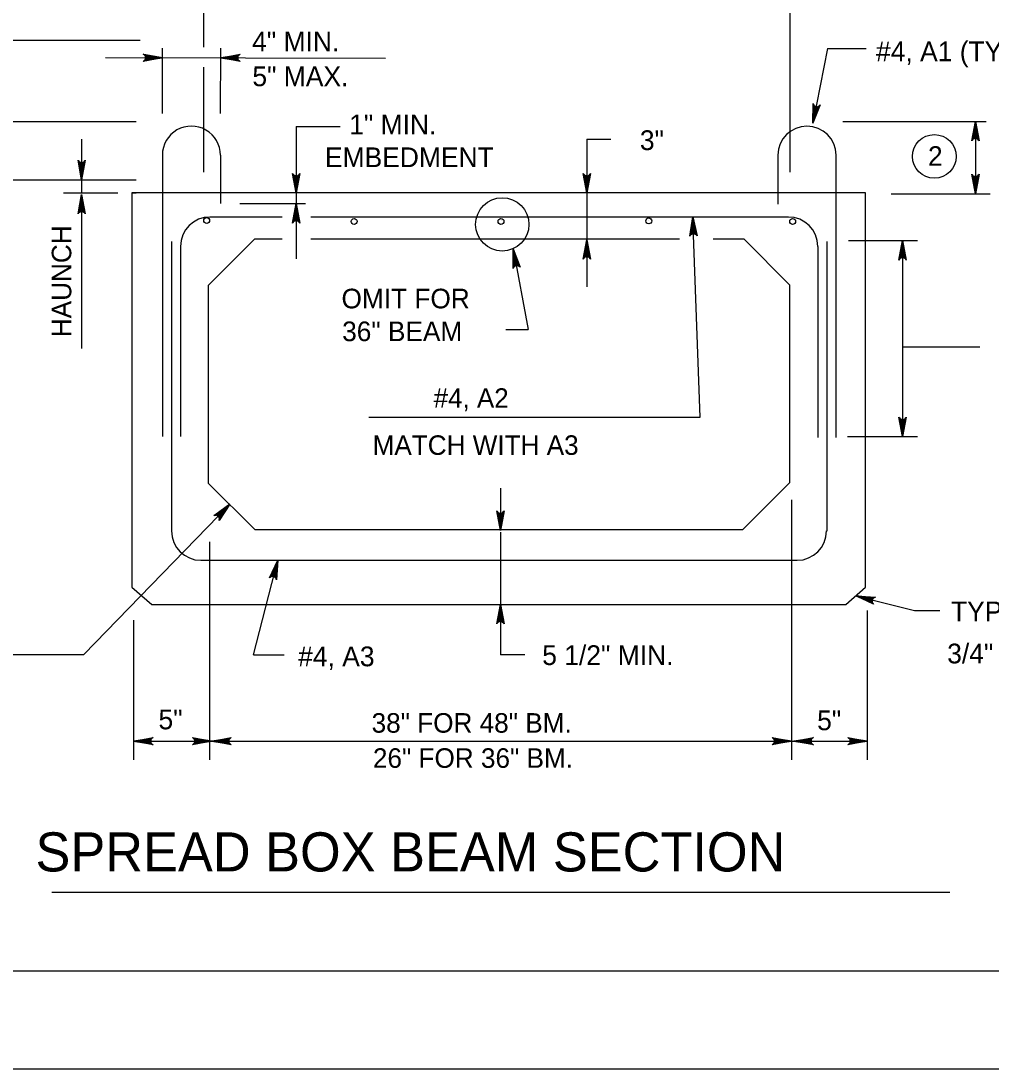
# Model space of a CAD drawing. Extents: x 639331 to 643089, y 299088 to 300975.
# Drawn here: x 641530.2 to 641679, y 299087.7 to 299248.4 of the extents above; entities that cross this region are included whole.
import ezdxf

# ---------------------------------------------------------------- set-up
doc = ezdxf.new("R2010")
doc.units = 0
doc.layers.add('1', color=7, linetype='Continuous')
doc.layers.add('PLT-BNDY', color=7, linetype='Continuous')

msp = doc.modelspace()

# ---------------------------------------------------------------- linework, layer by layer
at = {"layer": '1'}
for p, q in [((641558.17, 299256.75), (641558.17, 299244.44)), ((641648.09, 299256.75), (641648.09, 299225.23)), ((641548.44, 299245.44), (641512.84, 299245.44)), ((641551.86, 299234.24), (641551.88, 299244.3)), ((641560.77, 299234.23), (641560.79, 299244.28)), ((641653.87, 299244.2), (641651.62, 299232.75)), ((641653.87, 299244.2), (641659.79, 299244.2)), ((641543.1, 299242.82), (641586.08, 299242.75)), ((641558.17, 299241.34), (641558.17, 299225.23)), ((641512.84, 299233.04), (641547.81, 299233.04)), ((641656.21, 299233.04), (641678.19, 299233.04)), ((641676.55, 299233.04), (641676.55, 299221.95)), ((641572.36, 299232.24), (641579.09, 299232.24)), ((641572.36, 299232.24), (641572.36, 299220.42)), ((641539.46, 299230.34), (641539.46, 299222.08)), ((641616.95, 299230.29), (641620.61, 299230.29)), ((641616.95, 299230.29), (641616.95, 299222.08)), ((641551.84, 299227.86), (641551.84, 299184.69)), ((641560.75, 299227.85), (641560.75, 299220.42)), ((641646.26, 299227.86), (641646.26, 299220.36)), ((641655.17, 299227.86), (641655.17, 299184.57)), ((641512.84, 299224.1), (641547.81, 299224.1)), ((641536.69, 299222.08), (641545.03, 299222.08)), ((641539.46, 299221.83), (641539.46, 299198.2)), ((641659.71, 299222.08), (641547.18, 299222.08)), ((641547.18, 299222.08), (641547.18, 299161.58)), ((641547.18, 299222.08), (641547.81, 299222.08)), ((641616.95, 299222.08), (641616.95, 299215.01)), ((641659.71, 299161.58), (641659.71, 299222.08)), ((641663.62, 299221.95), (641678.8, 299221.95)), ((641563.74, 299220.42), (641573.78, 299220.42)), ((641572.36, 299220.42), (641572.36, 299211.97)), ((641559.14, 299218.42), (641570.23, 299218.42)), ((641574.64, 299218.42), (641647.87, 299218.42)), ((641634.33, 299187.69), (641633.19, 299218.42)), ((641558.8, 299218.16), (641558.8, 299218.16)), ((641581.28, 299218.04), (641581.28, 299218.04)), ((641603.89, 299217.91), (641603.89, 299217.91)), ((641626.37, 299217.78), (641626.37, 299217.78)), ((641648.97, 299217.66), (641648.97, 299217.66)), ((641551.84, 299214.63), (641551.84, 299184.69)), ((641553.24, 299214.63), (641553.24, 299170.17)), ((641554.64, 299213.87), (641554.64, 299184.69)), ((641558.92, 299207.93), (641566, 299215.01)), ((641566, 299215.01), (641570.23, 299215.01)), ((641574.64, 299215.01), (641631.17, 299215.01)), ((641616.95, 299215.01), (641616.95, 299207.68)), ((641636.33, 299215.01), (641641.02, 299215.01)), ((641641.02, 299215.01), (641648.09, 299207.93)), ((641652.37, 299213.87), (641652.37, 299184.57)), ((641653.77, 299214.63), (641653.77, 299170.17)), ((641657.09, 299214.75), (641667.66, 299214.75)), ((641665.39, 299214.75), (641665.39, 299184.68)), ((641605.65, 299213.49), (641607.93, 299201.11)), ((641558.92, 299177.5), (641558.92, 299207.93)), ((641648.09, 299177.62), (641648.09, 299207.93)), ((641604.52, 299201.11), (641607.93, 299201.11)), ((641665.39, 299198.46), (641677.24, 299198.46)), ((641583.52, 299187.69), (641634.33, 299187.69)), ((641656.93, 299184.68), (641667.66, 299184.68)), ((641558.92, 299177.5), (641566, 299170.42)), ((641603.69, 299176.76), (641603.69, 299170.3)), ((641640.89, 299170.42), (641648.09, 299177.62)), ((641562.21, 299174.34), (641539.79, 299151.28)), ((641648.34, 299174.97), (641648.34, 299135.12)), ((641566, 299170.42), (641640.89, 299170.42)), ((641603.69, 299170.04), (641603.69, 299158.93)), ((641559.05, 299168.53), (641559.05, 299135.12)), ((641557.79, 299165.75), (641649.22, 299165.75)), ((641565.81, 299151.18), (641569.53, 299165.75)), ((641547.18, 299161.58), (641550.21, 299158.93)), ((641656.68, 299158.93), (641659.71, 299161.58)), ((641550.21, 299158.93), (641656.68, 299158.93)), ((641603.69, 299158.93), (641603.69, 299158.8)), ((641603.69, 299158.93), (641603.69, 299151.18)), ((641658.19, 299160.26), (641667.19, 299157.98)), ((641659.96, 299158.02), (641659.96, 299135.12)), ((641667.19, 299157.98), (641671.12, 299157.98)), ((641547.43, 299156.53), (641547.43, 299135.12)), ((641524.47, 299151.28), (641539.79, 299151.28)), ((641565.81, 299151.18), (641570.54, 299151.18)), ((641607.46, 299151.18), (641603.69, 299151.18)), ((641547.43, 299137.96), (641559.43, 299137.96)), ((641559.43, 299137.96), (641648.72, 299137.96)), ((641648.72, 299137.96), (641659.96, 299137.96)), ((641672.61, 299114.74), (641534.91, 299114.74)), ((642219.06, 299102.66), (641433.06, 299102.66))]:
    msp.add_line(p, q, dxfattribs=at)
for points in [[(641551.88, 299242.81), (641548.89, 299242.25), (641549.01, 299242.33), (641549.12, 299242.41), (641549.18, 299242.51), (641549.24, 299242.61), (641549.26, 299242.71), (641549.28, 299242.81), (641549.26, 299242.91), (641549.24, 299243.01), (641549.18, 299243.11), (641549.12, 299243.21), (641549.01, 299243.29), (641548.9, 299243.37), (641551.88, 299242.81), (641549.01, 299243.29), (641549.12, 299243.21), (641551.88, 299242.81), (641549.18, 299243.11), (641549.24, 299243.01), (641551.88, 299242.81), (641549.26, 299242.91), (641549.28, 299242.81), (641551.88, 299242.81), (641549.26, 299242.71), (641549.24, 299242.61), (641551.88, 299242.81), (641549.18, 299242.51), (641549.12, 299242.41), (641551.88, 299242.81), (641549.01, 299242.33)], [(641560.79, 299242.79), (641563.77, 299243.35), (641563.66, 299243.27), (641563.54, 299243.19), (641563.48, 299243.09), (641563.42, 299242.99), (641563.4, 299242.89), (641563.39, 299242.79), (641563.4, 299242.69), (641563.42, 299242.59), (641563.48, 299242.49), (641563.54, 299242.39), (641563.65, 299242.31), (641563.77, 299242.23), (641560.79, 299242.79), (641563.65, 299242.31), (641563.54, 299242.39), (641560.79, 299242.79), (641563.48, 299242.49), (641563.42, 299242.59), (641560.79, 299242.79), (641563.4, 299242.69), (641563.39, 299242.79), (641560.79, 299242.79), (641563.4, 299242.89), (641563.42, 299242.99), (641560.79, 299242.79), (641563.48, 299243.09), (641563.54, 299243.19), (641560.79, 299242.79), (641563.66, 299243.27)], [(641651.62, 299232.75), (641651.65, 299235.79), (641651.7, 299235.66), (641651.76, 299235.53), (641651.85, 299235.45), (641651.93, 299235.38), (641652.03, 299235.34), (641652.12, 299235.3), (641652.22, 299235.3), (641652.33, 299235.3), (641652.43, 299235.34), (641652.54, 299235.38), (641652.64, 299235.48), (641652.74, 299235.57), (641651.62, 299232.75), (641652.64, 299235.48), (641652.54, 299235.38), (641651.62, 299232.75), (641652.43, 299235.34), (641652.33, 299235.3), (641651.62, 299232.75), (641652.22, 299235.3), (641652.12, 299235.3), (641651.62, 299232.75), (641652.03, 299235.34), (641651.93, 299235.38), (641651.62, 299232.75), (641651.85, 299235.45), (641651.76, 299235.53), (641651.62, 299232.75), (641651.7, 299235.66)], [(641676.55, 299233.04), (641677.11, 299230.06), (641677.03, 299230.17), (641676.95, 299230.29), (641676.85, 299230.35), (641676.75, 299230.41), (641676.65, 299230.42), (641676.55, 299230.44), (641676.45, 299230.42), (641676.35, 299230.41), (641676.25, 299230.35), (641676.15, 299230.29), (641676.07, 299230.17), (641675.99, 299230.06), (641676.55, 299233.04), (641676.07, 299230.17), (641676.15, 299230.29), (641676.55, 299233.04), (641676.25, 299230.35), (641676.35, 299230.41), (641676.55, 299233.04), (641676.45, 299230.42), (641676.55, 299230.44), (641676.55, 299233.04), (641676.65, 299230.42), (641676.75, 299230.41), (641676.55, 299233.04), (641676.85, 299230.35), (641676.95, 299230.29), (641676.55, 299233.04), (641677.03, 299230.17)], [(641539.46, 299224.1), (641538.91, 299227.08), (641538.98, 299226.97), (641539.06, 299226.85), (641539.16, 299226.79), (641539.26, 299226.73), (641539.36, 299226.72), (641539.46, 299226.7), (641539.56, 299226.72), (641539.66, 299226.73), (641539.76, 299226.79), (641539.86, 299226.85), (641539.94, 299226.97), (641540.02, 299227.08), (641539.46, 299224.1), (641539.94, 299226.97), (641539.86, 299226.85), (641539.46, 299224.1), (641539.76, 299226.79), (641539.66, 299226.73), (641539.46, 299224.1), (641539.56, 299226.72), (641539.46, 299226.7), (641539.46, 299224.1), (641539.36, 299226.72), (641539.26, 299226.73), (641539.46, 299224.1), (641539.16, 299226.79), (641539.06, 299226.85), (641539.46, 299224.1), (641538.98, 299226.97)], [(641572.36, 299222.08), (641571.8, 299225.06), (641571.88, 299224.95), (641571.96, 299224.83), (641572.06, 299224.77), (641572.16, 299224.71), (641572.26, 299224.7), (641572.36, 299224.68), (641572.46, 299224.7), (641572.56, 299224.71), (641572.66, 299224.77), (641572.76, 299224.83), (641572.84, 299224.95), (641572.92, 299225.06), (641572.36, 299222.08), (641572.84, 299224.95), (641572.76, 299224.83), (641572.36, 299222.08), (641572.66, 299224.77), (641572.56, 299224.71), (641572.36, 299222.08), (641572.46, 299224.7), (641572.36, 299224.68), (641572.36, 299222.08), (641572.26, 299224.7), (641572.16, 299224.71), (641572.36, 299222.08), (641572.06, 299224.77), (641571.96, 299224.83), (641572.36, 299222.08), (641571.88, 299224.95)], [(641616.95, 299222.08), (641616.39, 299225.06), (641616.47, 299224.95), (641616.55, 299224.83), (641616.65, 299224.77), (641616.75, 299224.71), (641616.85, 299224.7), (641616.95, 299224.68), (641617.05, 299224.7), (641617.15, 299224.71), (641617.25, 299224.77), (641617.35, 299224.83), (641617.43, 299224.95), (641617.51, 299225.06), (641616.95, 299222.08), (641617.43, 299224.95), (641617.35, 299224.83), (641616.95, 299222.08), (641617.25, 299224.77), (641617.15, 299224.71), (641616.95, 299222.08), (641617.05, 299224.7), (641616.95, 299224.68), (641616.95, 299222.08), (641616.85, 299224.7), (641616.75, 299224.71), (641616.95, 299222.08), (641616.65, 299224.77), (641616.55, 299224.83), (641616.95, 299222.08), (641616.47, 299224.95)], [(641676.55, 299221.95), (641675.99, 299224.93), (641676.07, 299224.82), (641676.15, 299224.7), (641676.25, 299224.65), (641676.35, 299224.59), (641676.45, 299224.57), (641676.55, 299224.55), (641676.65, 299224.57), (641676.75, 299224.59), (641676.85, 299224.65), (641676.95, 299224.7), (641677.03, 299224.82), (641677.11, 299224.93), (641676.55, 299221.95), (641677.03, 299224.82), (641676.95, 299224.7), (641676.55, 299221.95), (641676.85, 299224.65), (641676.75, 299224.59), (641676.55, 299221.95), (641676.65, 299224.57), (641676.55, 299224.55), (641676.55, 299221.95), (641676.45, 299224.57), (641676.35, 299224.59), (641676.55, 299221.95), (641676.25, 299224.65), (641676.15, 299224.7), (641676.55, 299221.95), (641676.07, 299224.82)], [(641539.46, 299221.83), (641540.02, 299218.84), (641539.94, 299218.96), (641539.86, 299219.07), (641539.76, 299219.13), (641539.66, 299219.19), (641539.56, 299219.21), (641539.46, 299219.22), (641539.36, 299219.21), (641539.26, 299219.19), (641539.16, 299219.13), (641539.06, 299219.07), (641538.98, 299218.96), (641538.91, 299218.84), (641539.46, 299221.83), (641538.98, 299218.96), (641539.06, 299219.07), (641539.46, 299221.83), (641539.16, 299219.13), (641539.26, 299219.19), (641539.46, 299221.83), (641539.36, 299219.21), (641539.46, 299219.22), (641539.46, 299221.83), (641539.56, 299219.21), (641539.66, 299219.19), (641539.46, 299221.83), (641539.76, 299219.13), (641539.86, 299219.07), (641539.46, 299221.83), (641539.94, 299218.96)], [(641572.36, 299220.42), (641572.92, 299217.43), (641572.84, 299217.55), (641572.76, 299217.66), (641572.66, 299217.72), (641572.56, 299217.78), (641572.46, 299217.8), (641572.36, 299217.82), (641572.26, 299217.8), (641572.16, 299217.78), (641572.06, 299217.72), (641571.96, 299217.66), (641571.88, 299217.55), (641571.8, 299217.43), (641572.36, 299220.42), (641571.88, 299217.55), (641571.96, 299217.66), (641572.36, 299220.42), (641572.06, 299217.72), (641572.16, 299217.78), (641572.36, 299220.42), (641572.26, 299217.8), (641572.36, 299217.82), (641572.36, 299220.42), (641572.46, 299217.8), (641572.56, 299217.78), (641572.36, 299220.42), (641572.66, 299217.72), (641572.76, 299217.66), (641572.36, 299220.42), (641572.84, 299217.55)], [(641633.19, 299218.42), (641633.86, 299215.46), (641633.77, 299215.57), (641633.69, 299215.68), (641633.59, 299215.73), (641633.48, 299215.79), (641633.38, 299215.8), (641633.28, 299215.82), (641633.18, 299215.8), (641633.08, 299215.77), (641632.99, 299215.71), (641632.89, 299215.65), (641632.81, 299215.53), (641632.74, 299215.41), (641633.19, 299218.42), (641632.81, 299215.53), (641632.89, 299215.65), (641633.19, 299218.42), (641632.99, 299215.71), (641633.08, 299215.77), (641633.19, 299218.42), (641633.18, 299215.8), (641633.28, 299215.82), (641633.19, 299218.42), (641633.38, 299215.8), (641633.48, 299215.79), (641633.19, 299218.42), (641633.59, 299215.73), (641633.69, 299215.68), (641633.19, 299218.42), (641633.77, 299215.57)], [(641616.95, 299214.88), (641617.51, 299211.9), (641617.43, 299212.01), (641617.35, 299212.13), (641617.25, 299212.19), (641617.15, 299212.24), (641617.05, 299212.26), (641616.95, 299212.28), (641616.85, 299212.26), (641616.75, 299212.24), (641616.65, 299212.19), (641616.55, 299212.13), (641616.47, 299212.01), (641616.39, 299211.9), (641616.95, 299214.88), (641616.47, 299212.01), (641616.55, 299212.13), (641616.95, 299214.88), (641616.65, 299212.19), (641616.75, 299212.24), (641616.95, 299214.88), (641616.85, 299212.26), (641616.95, 299212.28), (641616.95, 299214.88), (641617.05, 299212.26), (641617.15, 299212.24), (641616.95, 299214.88), (641617.25, 299212.19), (641617.35, 299212.13), (641616.95, 299214.88), (641617.43, 299212.01)], [(641665.39, 299214.75), (641665.95, 299211.77), (641665.87, 299211.88), (641665.79, 299212), (641665.69, 299212.06), (641665.59, 299212.12), (641665.49, 299212.14), (641665.39, 299212.15), (641665.29, 299212.14), (641665.19, 299212.12), (641665.09, 299212.06), (641664.99, 299212), (641664.91, 299211.88), (641664.83, 299211.77), (641665.39, 299214.75), (641664.91, 299211.88), (641664.99, 299212), (641665.39, 299214.75), (641665.09, 299212.06), (641665.19, 299212.12), (641665.39, 299214.75), (641665.29, 299212.14), (641665.39, 299212.15), (641665.39, 299214.75), (641665.49, 299212.14), (641665.59, 299212.12), (641665.39, 299214.75), (641665.69, 299212.06), (641665.79, 299212), (641665.39, 299214.75), (641665.87, 299211.88)], [(641605.65, 299213.49), (641606.74, 299210.66), (641606.64, 299210.76), (641606.54, 299210.85), (641606.44, 299210.89), (641606.33, 299210.93), (641606.22, 299210.93), (641606.12, 299210.93), (641606.03, 299210.9), (641605.93, 299210.86), (641605.84, 299210.79), (641605.76, 299210.71), (641605.7, 299210.58), (641605.64, 299210.45), (641605.65, 299213.49), (641605.7, 299210.58), (641605.76, 299210.71), (641605.65, 299213.49), (641605.84, 299210.79), (641605.93, 299210.86), (641605.65, 299213.49), (641606.03, 299210.9), (641606.12, 299210.93), (641605.65, 299213.49), (641606.22, 299210.93), (641606.33, 299210.93), (641605.65, 299213.49), (641606.44, 299210.89), (641606.54, 299210.85), (641605.65, 299213.49), (641606.64, 299210.76)], [(641665.39, 299184.68), (641664.83, 299187.66), (641664.91, 299187.55), (641664.99, 299187.43), (641665.09, 299187.37), (641665.19, 299187.31), (641665.29, 299187.3), (641665.39, 299187.28), (641665.49, 299187.3), (641665.59, 299187.31), (641665.69, 299187.37), (641665.79, 299187.43), (641665.87, 299187.55), (641665.95, 299187.66), (641665.39, 299184.68), (641665.87, 299187.55), (641665.79, 299187.43), (641665.39, 299184.68), (641665.69, 299187.37), (641665.59, 299187.31), (641665.39, 299184.68), (641665.49, 299187.3), (641665.39, 299187.28), (641665.39, 299184.68), (641665.29, 299187.3), (641665.19, 299187.31), (641665.39, 299184.68), (641665.09, 299187.37), (641664.99, 299187.43), (641665.39, 299184.68), (641664.91, 299187.55)], [(641562.21, 299174.34), (641560.53, 299171.81), (641560.55, 299171.95), (641560.58, 299172.09), (641560.55, 299172.2), (641560.52, 299172.31), (641560.46, 299172.39), (641560.4, 299172.47), (641560.31, 299172.53), (641560.23, 299172.59), (641560.12, 299172.62), (641560, 299172.64), (641559.87, 299172.62), (641559.73, 299172.59), (641562.21, 299174.34), (641559.87, 299172.62), (641560, 299172.64), (641562.21, 299174.34), (641560.12, 299172.62), (641560.23, 299172.59), (641562.21, 299174.34), (641560.31, 299172.53), (641560.4, 299172.47), (641562.21, 299174.34), (641560.46, 299172.39), (641560.52, 299172.31), (641562.21, 299174.34), (641560.55, 299172.2), (641560.58, 299172.09), (641562.21, 299174.34), (641560.55, 299171.95)], [(641603.69, 299170.3), (641603.13, 299173.28), (641603.21, 299173.17), (641603.29, 299173.05), (641603.39, 299172.99), (641603.49, 299172.93), (641603.59, 299172.91), (641603.69, 299172.9), (641603.79, 299172.91), (641603.89, 299172.93), (641603.99, 299172.99), (641604.09, 299173.05), (641604.17, 299173.17), (641604.25, 299173.28), (641603.69, 299170.3), (641604.17, 299173.17), (641604.09, 299173.05), (641603.69, 299170.3), (641603.99, 299172.99), (641603.89, 299172.93), (641603.69, 299170.3), (641603.79, 299172.91), (641603.69, 299172.9), (641603.69, 299170.3), (641603.59, 299172.91), (641603.49, 299172.93), (641603.69, 299170.3), (641603.39, 299172.99), (641603.29, 299173.05), (641603.69, 299170.3), (641603.21, 299173.17)], [(641569.53, 299165.75), (641569.34, 299162.72), (641569.29, 299162.85), (641569.24, 299162.98), (641569.16, 299163.07), (641569.08, 299163.15), (641568.98, 299163.19), (641568.89, 299163.23), (641568.79, 299163.24), (641568.69, 299163.25), (641568.58, 299163.21), (641568.46, 299163.18), (641568.36, 299163.09), (641568.25, 299163), (641569.53, 299165.75), (641568.36, 299163.09), (641568.46, 299163.18), (641569.53, 299165.75), (641568.58, 299163.21), (641568.69, 299163.25), (641569.53, 299165.75), (641568.79, 299163.24), (641568.89, 299163.23), (641569.53, 299165.75), (641568.98, 299163.19), (641569.08, 299163.15), (641569.53, 299165.75), (641569.16, 299163.07), (641569.24, 299162.98), (641569.53, 299165.75), (641569.29, 299162.85)], [(641603.69, 299158.93), (641604.25, 299155.95), (641604.17, 299156.06), (641604.09, 299156.18), (641603.99, 299156.24), (641603.89, 299156.3), (641603.79, 299156.31), (641603.69, 299156.33), (641603.59, 299156.31), (641603.49, 299156.3), (641603.39, 299156.24), (641603.29, 299156.18), (641603.21, 299156.06), (641603.13, 299155.95), (641603.69, 299158.93), (641603.21, 299156.06), (641603.29, 299156.18), (641603.69, 299158.93), (641603.39, 299156.24), (641603.49, 299156.3), (641603.69, 299158.93), (641603.59, 299156.31), (641603.69, 299156.33), (641603.69, 299158.93), (641603.79, 299156.31), (641603.89, 299156.3), (641603.69, 299158.93), (641603.99, 299156.24), (641604.09, 299156.18), (641603.69, 299158.93), (641604.17, 299156.06)], [(641658.19, 299160.26), (641661.22, 299160.07), (641661.09, 299160.02), (641660.96, 299159.97), (641660.88, 299159.89), (641660.8, 299159.81), (641660.75, 299159.71), (641660.71, 299159.62), (641660.71, 299159.52), (641660.7, 299159.42), (641660.73, 299159.31), (641660.76, 299159.19), (641660.86, 299159.09), (641660.95, 299158.98), (641658.19, 299160.26), (641660.86, 299159.09), (641660.76, 299159.19), (641658.19, 299160.26), (641660.73, 299159.31), (641660.7, 299159.42), (641658.19, 299160.26), (641660.71, 299159.52), (641660.71, 299159.62), (641658.19, 299160.26), (641660.75, 299159.71), (641660.8, 299159.81), (641658.19, 299160.26), (641660.88, 299159.89), (641660.96, 299159.97), (641658.19, 299160.26), (641661.09, 299160.02)], [(641547.43, 299137.96), (641550.41, 299138.52), (641550.3, 299138.44), (641550.18, 299138.36), (641550.13, 299138.26), (641550.07, 299138.16), (641550.05, 299138.06), (641550.03, 299137.96), (641550.05, 299137.86), (641550.07, 299137.76), (641550.13, 299137.66), (641550.18, 299137.56), (641550.3, 299137.48), (641550.41, 299137.4), (641547.43, 299137.96), (641550.3, 299137.48), (641550.18, 299137.56), (641547.43, 299137.96), (641550.13, 299137.66), (641550.07, 299137.76), (641547.43, 299137.96), (641550.05, 299137.86), (641550.03, 299137.96), (641547.43, 299137.96), (641550.05, 299138.06), (641550.07, 299138.16), (641547.43, 299137.96), (641550.13, 299138.26), (641550.18, 299138.36), (641547.43, 299137.96), (641550.3, 299138.44)], [(641559.43, 299137.96), (641556.45, 299137.4), (641556.56, 299137.48), (641556.68, 299137.56), (641556.74, 299137.66), (641556.79, 299137.76), (641556.81, 299137.86), (641556.83, 299137.96), (641556.81, 299138.06), (641556.79, 299138.16), (641556.74, 299138.26), (641556.68, 299138.36), (641556.56, 299138.44), (641556.45, 299138.52), (641559.43, 299137.96), (641556.56, 299138.44), (641556.68, 299138.36), (641559.43, 299137.96), (641556.74, 299138.26), (641556.79, 299138.16), (641559.43, 299137.96), (641556.81, 299138.06), (641556.83, 299137.96), (641559.43, 299137.96), (641556.81, 299137.86), (641556.79, 299137.76), (641559.43, 299137.96), (641556.74, 299137.66), (641556.68, 299137.56), (641559.43, 299137.96), (641556.56, 299137.48)], [(641559.43, 299137.96), (641562.41, 299138.52), (641562.3, 299138.44), (641562.18, 299138.36), (641562.12, 299138.26), (641562.06, 299138.16), (641562.05, 299138.06), (641562.03, 299137.96), (641562.05, 299137.86), (641562.06, 299137.76), (641562.12, 299137.66), (641562.18, 299137.56), (641562.3, 299137.48), (641562.41, 299137.4), (641559.43, 299137.96), (641562.3, 299137.48), (641562.18, 299137.56), (641559.43, 299137.96), (641562.12, 299137.66), (641562.06, 299137.76), (641559.43, 299137.96), (641562.05, 299137.86), (641562.03, 299137.96), (641559.43, 299137.96), (641562.05, 299138.06), (641562.06, 299138.16), (641559.43, 299137.96), (641562.12, 299138.26), (641562.18, 299138.36), (641559.43, 299137.96), (641562.3, 299138.44)], [(641648.34, 299137.96), (641645.36, 299137.4), (641645.47, 299137.48), (641645.59, 299137.56), (641645.65, 299137.66), (641645.71, 299137.76), (641645.72, 299137.86), (641645.74, 299137.96), (641645.72, 299138.06), (641645.71, 299138.16), (641645.65, 299138.26), (641645.59, 299138.36), (641645.47, 299138.44), (641645.36, 299138.52), (641648.34, 299137.96), (641645.47, 299138.44), (641645.59, 299138.36), (641648.34, 299137.96), (641645.65, 299138.26), (641645.71, 299138.16), (641648.34, 299137.96), (641645.72, 299138.06), (641645.74, 299137.96), (641648.34, 299137.96), (641645.72, 299137.86), (641645.71, 299137.76), (641648.34, 299137.96), (641645.65, 299137.66), (641645.59, 299137.56), (641648.34, 299137.96), (641645.47, 299137.48)], [(641648.72, 299137.96), (641651.7, 299138.52), (641651.59, 299138.44), (641651.47, 299138.36), (641651.41, 299138.26), (641651.35, 299138.16), (641651.34, 299138.06), (641651.32, 299137.96), (641651.34, 299137.86), (641651.35, 299137.76), (641651.41, 299137.66), (641651.47, 299137.56), (641651.59, 299137.48), (641651.7, 299137.4), (641648.72, 299137.96), (641651.59, 299137.48), (641651.47, 299137.56), (641648.72, 299137.96), (641651.41, 299137.66), (641651.35, 299137.76), (641648.72, 299137.96), (641651.34, 299137.86), (641651.32, 299137.96), (641648.72, 299137.96), (641651.34, 299138.06), (641651.35, 299138.16), (641648.72, 299137.96), (641651.41, 299138.26), (641651.47, 299138.36), (641648.72, 299137.96), (641651.59, 299138.44)], [(641659.96, 299137.96), (641656.98, 299137.4), (641657.09, 299137.48), (641657.21, 299137.56), (641657.27, 299137.66), (641657.33, 299137.76), (641657.34, 299137.86), (641657.36, 299137.96), (641657.34, 299138.06), (641657.33, 299138.16), (641657.27, 299138.26), (641657.21, 299138.36), (641657.09, 299138.44), (641656.98, 299138.52), (641659.96, 299137.96), (641657.09, 299138.44), (641657.21, 299138.36), (641659.96, 299137.96), (641657.27, 299138.26), (641657.33, 299138.16), (641659.96, 299137.96), (641657.34, 299138.06), (641657.36, 299137.96), (641659.96, 299137.96), (641657.34, 299137.86), (641657.33, 299137.76), (641659.96, 299137.96), (641657.27, 299137.66), (641657.21, 299137.56), (641659.96, 299137.96), (641657.09, 299137.48)]]:
    msp.add_lwpolyline(points, dxfattribs=at)
for centre, radius in [((641670.26, 299227.67), 3.35), ((641603.98, 299217.24), 4.09), ((641558.64, 299217.84), 0.452), ((641581.25, 299217.69), 0.452), ((641603.78, 299217.69), 0.452), ((641626.45, 299217.77), 0.452), ((641648.52, 299217.69), 0.452)]:
    msp.add_circle(centre, radius, dxfattribs=at)
for centre, radius, start, end in [((641556.3, 299227.86), 4.46, 359.9442, 180.0003), ((641650.72, 299227.86), 4.46, 0, 179.9443), ((641559.14, 299213.87), 4.5, 90, 180), ((641647.87, 299213.87), 4.5, 0, 90), ((641557.73, 299170.21), 4.5, 180, 270), ((641649.21, 299170.21), 4.5, 270, 360)]:
    msp.add_arc(centre, radius, start, end, dxfattribs=at)
at = {"layer": 'PLT-BNDY'}
msp.add_lwpolyline([(641393.06, 299681.66), (642234.06, 299681.66), (642234.06, 299087.66), (641393.06, 299087.66)], close=True, dxfattribs=at)

# ---------------------------------------------------------------- texts
at = {"layer": '1'}
for s, height, rotation, p in [('4" MIN.', 3.031, 360, (641565.61, 299243.78)), ('5" MAX.', 3.031, 360, (641565.65, 299238.44)), ('HAUNCH', 3, 90, (641537.87, 299199.93))]:
    msp.add_text(s, height=height, rotation=rotation, dxfattribs=at).set_placement(p)
for s, height, p in [('#4, A1 (TYP.)', 3.0311, (641661.31, 299242.27)), ('1" MIN.', 3.031, (641580.5, 299231.05)), ('3"', 3.031, (641625.09, 299228.64)), ('EMBEDMENT', 3.031, (641576.78, 299226.02)), ('2', 3, (641669.29, 299226.23)), ('OMIT FOR', 3.01, (641579.32, 299204.36)), ('36" BEAM', 3.01, (641579.42, 299199.33)), ('#4, A2', 2.975, (641593.46, 299189.12)), ('MATCH WITH A3', 2.9962, (641584.09, 299181.88)), ('TYP. CHAMFER:', 3.0311, (641672.81, 299156.35)), ('#4, A3', 3.031, (641572.67, 299149.45)), ('5 1/2" MIN.', 3.0311, (641610.11, 299149.64)), ('3/4" x 3/4"', 3.0311, (641672.23, 299149.89)), ('5"', 3.031, (641551.25, 299139.78)), ('38" FOR 48" BM.', 2.9977, (641583.94, 299139.26)), ('5"', 3.031, (641652.28, 299139.64)), ('26" FOR 36" BM.', 2.9977, (641584.14, 299133.87)), (' SPREAD BOX BEAM SECTION ', 6, (641530.15, 299117.97))]:
    msp.add_text(s, height=height, dxfattribs=at).set_placement(p)

doc.saveas('drawing.dxf')
